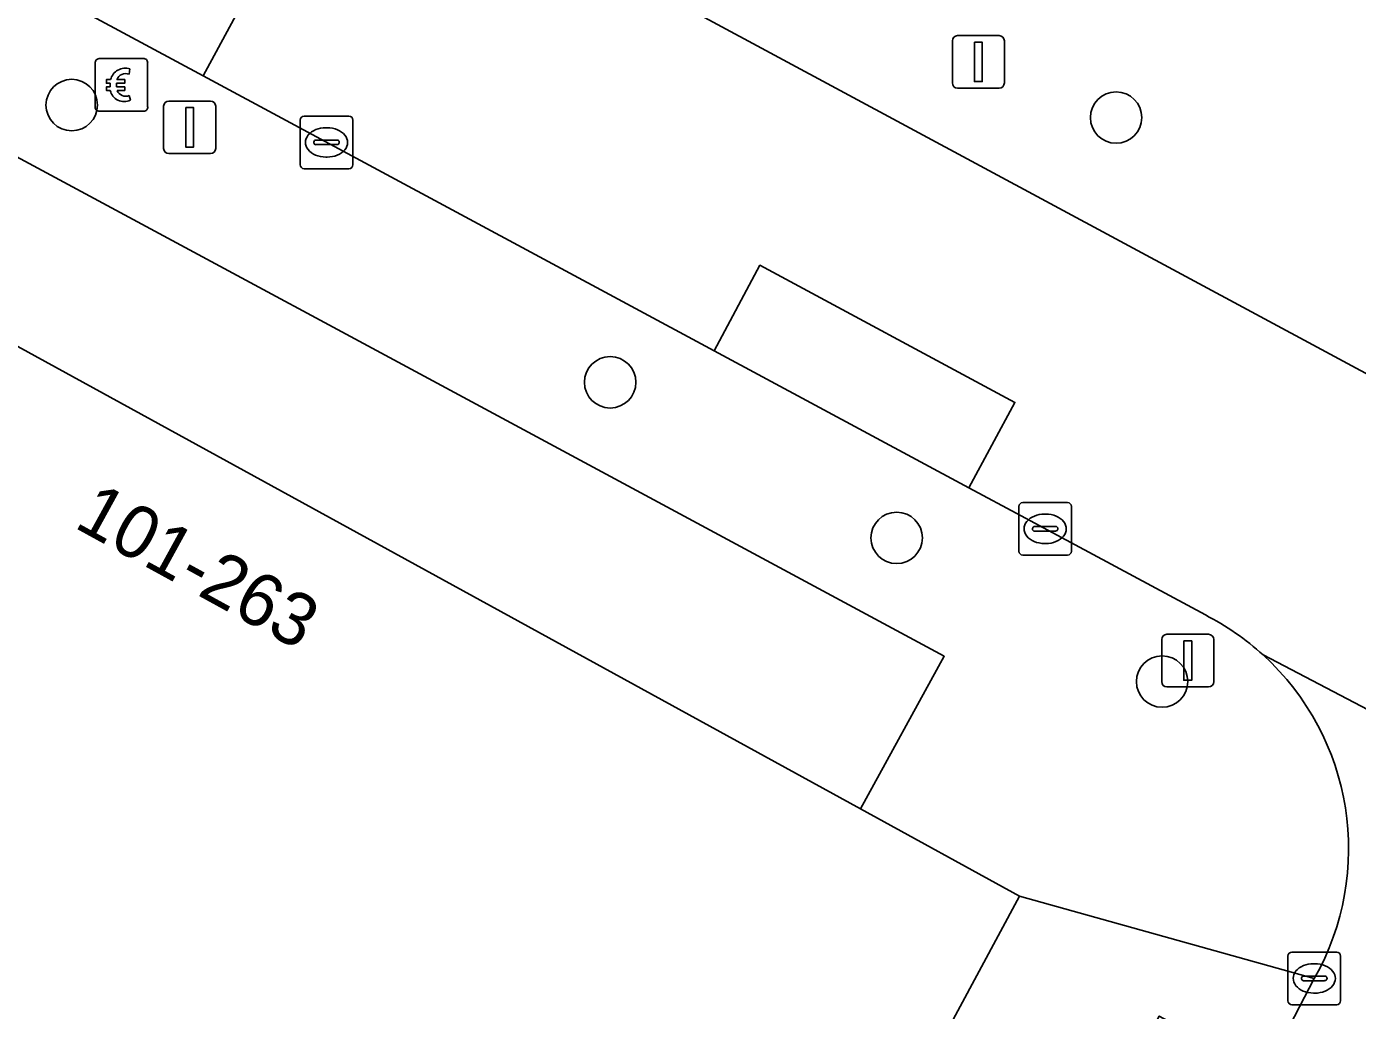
# Model space of a CAD drawing. Extents: x 159489 to 160304, y 383825 to 384531.
# Drawn here: x 159630.19 to 159655.5, y 384239.88 to 384258.59 of the extents above; entities that cross this region are included whole.
import ezdxf

# ---------------------------------------------------------------- set-up
doc = ezdxf.new("R2010")
doc.units = 0
for name, color, linetype in [('IMGEO_Betaalautomaat', 7, 'Continuous'), ('IMGEO_Boom', 7, 'Continuous'), ('IMGEO_Groenvoorziening', 7, 'Continuous'), ('IMGEO_Kolk', 7, 'Continuous'), ('IMGEO_Lichtmast', 7, 'Continuous'), ('IMGEO_Pand', 7, 'Continuous'), ('IMGEO_Pand_nummerreeks', 7, 'Continuous'), ('IMGEO_Pand_overbouw', 7, 'Continuous'), ('IMGEO_Parkeervlak_gesloten', 7, 'Continuous'), ('IMGEO_Rijbaan_lokaal_gesloten', 7, 'Continuous'), ('IMGEO_Voetpad_open', 7, 'Continuous')]:
    doc.layers.add(name, color=color, linetype=linetype)

msp = doc.modelspace()

# ---------------------------------------------------------------- linework, layer by layer
at = {"layer": 'IMGEO_Betaalautomaat'}
for p, q in [((159631.493, 384257.057), (159631.493, 384257.898)), ((159631.493, 384257.898), (159631.493, 384257.057)), ((159631.568, 384257.981), (159632.409, 384257.981)), ((159632.409, 384257.981), (159631.568, 384257.981)), ((159632.492, 384257.907), (159632.492, 384257.066)), ((159632.492, 384257.066), (159632.492, 384257.907)), ((159632.155, 384257.786), (159632.138, 384257.686)), ((159631.776, 384257.445), (159631.776, 384257.513)), ((159631.897, 384257.513), (159631.897, 384257.445)), ((159632.142, 384257.28), (159632.164, 384257.193)), ((159632.418, 384256.982), (159631.577, 384256.982)), ((159631.577, 384256.982), (159632.418, 384256.982))]:
    msp.add_line(p, q, dxfattribs=at)
for points in [[(159631.776, 384257.513), (159631.707, 384257.513), (159631.707, 384257.582), (159631.786, 384257.582)], [(159631.781, 384257.376), (159631.707, 384257.376), (159631.707, 384257.445), (159631.776, 384257.445)], [(159631.908, 384257.582), (159632.055, 384257.582), (159632.055, 384257.513), (159631.897, 384257.513)], [(159631.897, 384257.445), (159632.055, 384257.445), (159632.055, 384257.376), (159631.911, 384257.376)]]:
    msp.add_lwpolyline(points, dxfattribs=at)
for centre, radius, start, end in [((159631.571, 384257.904), 0.0779, 92.4484, 184.2845), ((159631.571, 384257.904), 0.0779, 92.4484, 184.2845), ((159632.415, 384257.904), 0.0779, 2.4484, 94.2845), ((159632.415, 384257.904), 0.0779, 2.4484, 94.2845), ((159632.069, 384257.506), 0.293, 73.014, 165.0139), ((159632.075, 384257.519), 0.179, 69.3236, 159.5683), ((159632.042, 384257.431), 0.267, 191.8096, 297.0389), ((159632.075, 384257.446), 0.179, 202.7625, 291.8693), ((159631.571, 384257.06), 0.0779, 182.4484, 274.2845), ((159631.571, 384257.06), 0.0779, 182.4484, 274.2845), ((159632.415, 384257.06), 0.0779, 272.4484, 4.2845), ((159632.415, 384257.06), 0.0779, 272.4484, 4.2845)]:
    msp.add_arc(centre, radius, start, end, dxfattribs=at)
at = {"layer": 'IMGEO_Boom'}
for centre in [(159631.047, 384257.099), (159650.914, 384256.86), (159641.29, 384251.824), (159646.74, 384248.864), (159651.788, 384246.131)]:
    msp.add_circle(centre, 0.489, dxfattribs=at)
at = {"layer": 'IMGEO_Groenvoorziening'}
msp.add_lwpolyline([(159653.655, 384278.383), (159643.082, 384258.763), (159687.782, 384234.713), (159702.031, 384227.047), (159699.72, 384254.238)], dxfattribs=at)
at = {"layer": 'IMGEO_Kolk'}
for p, q in [((159635.469, 384256.888), (159636.321, 384256.888)), ((159635.394, 384255.962), (159635.394, 384256.814)), ((159635.882, 384256.668), (159635.907, 384256.668)), ((159636.395, 384256.814), (159636.395, 384255.962)), ((159635.653, 384256.382), (159635.653, 384256.394)), ((159636.091, 384256.345), (159635.693, 384256.345)), ((159635.696, 384256.431), (159636.094, 384256.431)), ((159636.137, 384256.394), (159636.137, 384256.382)), ((159635.905, 384256.108), (159635.88, 384256.108)), ((159636.321, 384255.888), (159635.469, 384255.888)), ((159649.139, 384249.537), (159649.991, 384249.537)), ((159649.064, 384248.611), (159649.064, 384249.463)), ((159649.552, 384249.317), (159649.577, 384249.317)), ((159650.065, 384249.463), (159650.065, 384248.611)), ((159649.323, 384249.031), (159649.323, 384249.043)), ((159649.366, 384249.08), (159649.764, 384249.08)), ((159649.807, 384249.043), (159649.807, 384249.031)), ((159649.761, 384248.994), (159649.363, 384248.994)), ((159649.575, 384248.757), (159649.55, 384248.757)), ((159649.991, 384248.537), (159649.139, 384248.537)), ((159654.183, 384240.058), (159654.183, 384240.91)), ((159654.258, 384240.984), (159655.11, 384240.984)), ((159655.184, 384240.91), (159655.184, 384240.058)), ((159654.671, 384240.764), (159654.696, 384240.764)), ((159654.442, 384240.478), (159654.442, 384240.49)), ((159654.88, 384240.441), (159654.482, 384240.441)), ((159654.485, 384240.527), (159654.883, 384240.527)), ((159654.926, 384240.49), (159654.926, 384240.478)), ((159654.694, 384240.204), (159654.669, 384240.204)), ((159655.11, 384239.984), (159654.258, 384239.984))]:
    msp.add_line(p, q, dxfattribs=at)
for points in [[(159635.469, 384256.888), (159636.321, 384256.888)], [(159635.394, 384255.962), (159635.394, 384256.814)], [(159636.395, 384256.814), (159636.395, 384255.962)], [(159636.321, 384255.888), (159635.469, 384255.888)], [(159649.139, 384249.537), (159649.991, 384249.537)], [(159649.064, 384248.611), (159649.064, 384249.463)], [(159650.065, 384249.463), (159650.065, 384248.611)], [(159649.991, 384248.537), (159649.139, 384248.537)], [(159654.183, 384240.058), (159654.183, 384240.91)], [(159654.258, 384240.984), (159655.11, 384240.984)], [(159655.184, 384240.91), (159655.184, 384240.058)], [(159655.11, 384239.984), (159654.258, 384239.984)]]:
    msp.add_lwpolyline(points, dxfattribs=at)
for centre, radius, start, end in [((159635.471, 384256.812), 0.0765, 91.552, 178.448), ((159635.471, 384256.812), 0.0765, 91.552, 178.448), ((159636.319, 384256.812), 0.0765, 1.552, 88.448), ((159636.319, 384256.812), 0.0765, 1.552, 88.448), ((159635.693, 384256.391), 0.0403, 85.8775, 175.7526), ((159635.69, 384256.381), 0.0366, 178.938, 274.7102), ((159636.094, 384256.388), 0.043, 264.8664, 352.4533), ((159636.098, 384256.393), 0.0386, 1.7309, 96.639), ((159635.471, 384255.964), 0.0765, 181.552, 268.448), ((159635.471, 384255.964), 0.0765, 181.552, 268.448), ((159636.319, 384255.964), 0.0765, 271.552, 358.448), ((159636.319, 384255.964), 0.0765, 271.552, 358.448), ((159649.141, 384249.461), 0.0765, 91.552, 178.448), ((159649.141, 384249.461), 0.0765, 91.552, 178.448), ((159649.989, 384249.461), 0.0765, 1.552, 88.448), ((159649.989, 384249.461), 0.0765, 1.552, 88.448), ((159649.363, 384249.04), 0.0403, 85.8775, 175.7526), ((159649.36, 384249.03), 0.0366, 178.938, 274.7102), ((159649.764, 384249.037), 0.043, 264.8664, 352.4533), ((159649.768, 384249.042), 0.0386, 1.7309, 96.639), ((159649.141, 384248.613), 0.0765, 181.552, 268.448), ((159649.141, 384248.613), 0.0765, 181.552, 268.448), ((159649.989, 384248.613), 0.0765, 271.552, 358.448), ((159649.989, 384248.613), 0.0765, 271.552, 358.448), ((159654.26, 384240.908), 0.0765, 91.552, 178.448), ((159654.26, 384240.908), 0.0765, 91.552, 178.448), ((159655.108, 384240.908), 0.0765, 1.552, 88.448), ((159655.108, 384240.908), 0.0765, 1.552, 88.448), ((159654.482, 384240.487), 0.0403, 85.8775, 175.7526), ((159654.479, 384240.477), 0.0366, 178.938, 274.7102), ((159654.883, 384240.484), 0.043, 264.8664, 352.4533), ((159654.887, 384240.489), 0.0386, 1.7309, 96.639), ((159654.26, 384240.06), 0.0765, 181.552, 268.448), ((159654.26, 384240.06), 0.0765, 181.552, 268.448), ((159655.108, 384240.06), 0.0765, 271.552, 358.448), ((159655.108, 384240.06), 0.0765, 271.552, 358.448)]:
    msp.add_arc(centre, radius, start, end, dxfattribs=at)
for centre, major_axis, ratio, start_param, end_param in [((159635.881, 384256.388), (-0.387, 0.002), 0.722429, 4.712389, 7.853982), ((159635.906, 384256.388), (-0.39, 0.002), 0.717154, 1.570796, 4.712389), ((159649.551, 384249.037), (-0.387, 0.002), 0.722429, 4.712389, 7.853982), ((159649.576, 384249.037), (-0.39, 0.002), 0.717154, 1.570796, 4.712389), ((159654.67, 384240.484), (-0.387, 0.002), 0.722429, 4.712389, 7.853982), ((159654.695, 384240.484), (-0.39, 0.002), 0.717154, 1.570796, 4.712389)]:
    msp.add_ellipse(centre, major_axis=major_axis, ratio=ratio, start_param=start_param, end_param=end_param, dxfattribs=at)
at = {"layer": 'IMGEO_Lichtmast'}
for p, q in [((159647.899, 384258.419), (159648.689, 384258.419)), ((159648.689, 384258.419), (159647.899, 384258.419)), ((159647.799, 384257.519), (159647.799, 384258.319)), ((159647.799, 384258.319), (159647.799, 384257.519)), ((159648.789, 384258.319), (159648.789, 384257.519)), ((159648.789, 384257.519), (159648.789, 384258.319)), ((159648.689, 384257.419), (159647.899, 384257.419)), ((159647.899, 384257.419), (159648.689, 384257.419)), ((159632.896, 384257.175), (159633.686, 384257.175)), ((159633.686, 384257.175), (159632.896, 384257.175)), ((159632.796, 384256.275), (159632.796, 384257.075)), ((159632.796, 384257.075), (159632.796, 384256.275)), ((159633.786, 384257.075), (159633.786, 384256.275)), ((159633.786, 384256.275), (159633.786, 384257.075)), ((159633.686, 384256.175), (159632.896, 384256.175)), ((159632.896, 384256.175), (159633.686, 384256.175)), ((159651.882, 384247.03), (159652.672, 384247.03)), ((159652.672, 384247.03), (159651.882, 384247.03)), ((159651.782, 384246.13), (159651.782, 384246.93)), ((159651.782, 384246.93), (159651.782, 384246.13)), ((159652.772, 384246.93), (159652.772, 384246.13)), ((159652.772, 384246.13), (159652.772, 384246.93)), ((159652.672, 384246.03), (159651.882, 384246.03)), ((159651.882, 384246.03), (159652.672, 384246.03))]:
    msp.add_line(p, q, dxfattribs=at)
for points in [[(159648.219, 384258.294), (159648.369, 384258.294), (159648.369, 384257.544), (159648.219, 384257.544), (159648.219, 384258.294)], [(159633.216, 384257.05), (159633.366, 384257.05), (159633.366, 384256.3), (159633.216, 384256.3), (159633.216, 384257.05)], [(159652.202, 384246.905), (159652.352, 384246.905), (159652.352, 384246.155), (159652.202, 384246.155), (159652.202, 384246.905)]]:
    msp.add_lwpolyline(points, dxfattribs=at)
for centre, start, end in [((159647.899, 384258.319), 90, 180), ((159647.899, 384258.319), 90, 180), ((159648.689, 384258.319), 0, 90), ((159648.689, 384258.319), 360, 90), ((159647.899, 384257.519), 180, 270), ((159647.899, 384257.519), 180, 270), ((159648.689, 384257.519), 270, 0), ((159648.689, 384257.519), 270, 0), ((159632.896, 384257.075), 90, 180), ((159632.896, 384257.075), 90, 180), ((159633.686, 384257.075), 0, 90), ((159633.686, 384257.075), 360, 90), ((159632.896, 384256.275), 180, 270), ((159632.896, 384256.275), 180, 270), ((159633.686, 384256.275), 270, 0), ((159633.686, 384256.275), 270, 0), ((159651.882, 384246.93), 90, 180), ((159651.882, 384246.93), 90, 180), ((159652.672, 384246.93), 0, 90), ((159652.672, 384246.93), 360, 90), ((159651.882, 384246.13), 180, 270), ((159651.882, 384246.13), 180, 270), ((159652.672, 384246.13), 270, 0), ((159652.672, 384246.13), 270, 0)]:
    msp.add_arc(centre, 0.1, start, end, dxfattribs=at)
at = {"layer": 'IMGEO_Pand'}
msp.add_lwpolyline([(159649.079, 384242.048), (159646.05, 384243.709), (159621.346, 384257.26), (159621.017, 384257.441), (159620.712, 384257.605), (159616.379, 384249.69), (159611.777, 384241.285), (159640.276, 384225.681)], close=True, dxfattribs=at)
at = {"layer": 'IMGEO_Pand_overbouw'}
msp.add_lwpolyline([(159621.346, 384257.26), (159646.05, 384243.709), (159647.644, 384246.614), (159622.814, 384259.985)], close=True, dxfattribs=at)
at = {"layer": 'IMGEO_Parkeervlak_gesloten'}
for points in [[(159610.125, 384270.247), (159633.545, 384257.652), (159634.42, 384259.278), (159610.999, 384271.873)], [(159643.266, 384252.424), (159648.115, 384249.816), (159648.99, 384251.442), (159644.14, 384254.05)]]:
    msp.add_lwpolyline(points, close=True, dxfattribs=at)
at = {"layer": 'IMGEO_Rijbaan_lokaal_gesloten'}
for points in [[(159524.477, 384316.223), (159526.867, 384315.023), (159527.963, 384314.433), (159535.565, 384310.345), (159536.44, 384311.971), (159549.851, 384304.759), (159550.324, 384304.504), (159549.449, 384302.878), (159558.914, 384297.788), (159559.789, 384299.414), (159596.815, 384279.502), (159606.884, 384274.087), (159606.009, 384272.461), (159610.125, 384270.247), (159610.999, 384271.873), (159634.42, 384259.278), (159633.545, 384257.652), (159643.266, 384252.424), (159644.14, 384254.05), (159648.99, 384251.442), (159648.115, 384249.816), (159649.108, 384249.282), (159652.612, 384247.398)], [(159653.711, 384246.637), (159666.397, 384239.997), (159671.595, 384237.203), (159672.497, 384238.902), (159686.109, 384231.571), (159687.782, 384234.713), (159643.082, 384258.763)], [(159666.397, 384239.997), (159653.711, 384246.637)], [(159654.684, 384240.484), (159653.747, 384238.682), (159646.166, 384224.11), (159643.655, 384219.446), (159639.366, 384211.481), (159638.312, 384209.524), (159635.354, 384204.03), (159631.805, 384197.437), (159631.422, 384196.726), (159624.053, 384183.005), (159617.514, 384170.805), (159617.293, 384170.392), (159616.523, 384168.93), (159615.471, 384167.017)]]:
    msp.add_lwpolyline(points, dxfattribs=at)
for centre, radius, start, end in [((159650.318, 384242.911), 5.039, 47.677, 62.9218), ((159650.343, 384242.951), 4.993, 330.3891, 47.5829)]:
    msp.add_arc(centre, radius, start, end, dxfattribs=at)
at = {"layer": 'IMGEO_Voetpad_open'}
for points in [[(159652.612, 384247.398), (159649.108, 384249.282), (159648.115, 384249.816), (159643.266, 384252.424), (159633.545, 384257.652), (159610.125, 384270.247), (159606.009, 384272.461), (159595.94, 384277.876), (159558.914, 384297.788), (159549.449, 384302.878), (159535.565, 384310.345), (159527.963, 384314.433)], [(159514.758, 384298.232), (159516.4, 384294.599), (159517.502, 384296.664), (159524.97, 384310.657), (159525.855, 384310.207), (159526.055, 384310.099), (159576.611, 384282.913), (159575.933, 384281.657), (159590.223, 384274), (159620.712, 384257.605), (159621.017, 384257.441), (159621.346, 384257.26), (159646.05, 384243.709), (159649.079, 384242.048), (159654.684, 384240.484)], [(159637.113, 384212.661), (159639.366, 384211.481), (159643.655, 384219.446), (159641.422, 384220.631), (159651.736, 384239.768), (159653.747, 384238.682), (159654.684, 384240.484), (159649.079, 384242.048), (159640.276, 384225.681), (159631.56, 384209.476), (159627.071, 384201.275), (159614.197, 384177.327), (159611.986, 384173.213), (159610.792, 384170.994), (159596.345, 384167.614), (159594.181, 384167.108), (159595.735, 384164.295)]]:
    msp.add_lwpolyline(points, dxfattribs=at)
for centre, radius, start, end in [((159650.318, 384242.911), 5.039, 47.677, 62.9218), ((159650.343, 384242.951), 4.993, 330.3891, 47.5829)]:
    msp.add_arc(centre, radius, start, end, dxfattribs=at)

# ---------------------------------------------------------------- texts
at = {"layer": 'IMGEO_Pand_nummerreeks'}
msp.add_text('101-263', height=1, rotation=331.2432, dxfattribs=at).set_placement((159631.067, 384249.077))

doc.saveas('drawing.dxf')
